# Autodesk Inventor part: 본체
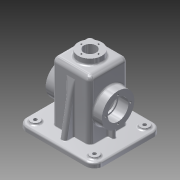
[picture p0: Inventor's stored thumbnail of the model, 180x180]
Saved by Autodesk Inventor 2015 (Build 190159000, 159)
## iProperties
Created: 2016-02
Part Number: 본체
Material: 알루미늄 6061
Document SubType Name: Modeling
Designer: Administrator
Density: 2.7 g/cm^3
Appearance: 알루미늄 - 평지
Mass: 799.421 g
Surface Area: 907.841 cm^2
Volume: 296.082 cm^3
Author: Administrator
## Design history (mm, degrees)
sketch "스케치1"
  geometry: L1 (-65, 57.5)-(65, 57.5); L2 (65, 57.5)-(65, -57.5); L3 (65, -57.5)-(-65, -57.5); L4 (-65, -57.5)-(-65, 57.5); L5 (-65, 57.5)-(65, -57.5); L6 (65, 57.5)-(-65, -57.5); 1 further point
  constraints: 12 end point, 2 midpoint, 2 parallel, 1 horizontal, 1 perpendicular
  dimensions: "d0" = 130 distance of L2.end L3.end; "d1" = 115 distance of L1.end L2.end
extrude "돌출1" new body sketch "스케치1" distance "d2" = 8; taper "d3" = 0 deg
sketch "스케치2"
  geometry: L1 (-32.5, 32.5)-(32.5, 32.5); L2 (32.5, 32.5)-(32.5, -32.5); L3 (32.5, -32.5)-(-32.5, -32.5); L4 (-32.5, -32.5)-(-32.5, 32.5); L5 (-32.5, 32.5)-(32.5, -32.5); L6 (32.5, 32.5)-(-32.5, -32.5); 1 further point
  constraints: 12 end point, 2 midpoint, 2 parallel, 1 horizontal, 1 perpendicular
  dimensions: "d4" = 65 distance of L2.end L3.end; "d5" = 65 distance of L1.end L2.end
extrude "돌출2" join sketch "스케치2" distance "d6" = 100; taper "d7" = 0 deg
sketch "스케치5"
  geometry: C1 r 20 at (0, 0); 1 further point
  constraints: 1 centre point, 1 coincident
  dimensions: "d16" = 40 diameter of C1
extrude "돌출5" join sketch "스케치5" distance "d17" = 10; taper "d18" = 0 deg
sketch "스케치7"
  geometry: L1 (-42.5, 32.753)-(-42.5, 8); L2 (65, 8)-(-65, 8) reference; L3 (-42.5, 32.753)-(42.5, 32.753); L4 (42.5, 32.753)-(42.5, 8); L5 (-32.5, 8)-(-32.5, 108) reference; 3 further points
  constraints: 6 end point, 2 point on line, 1 horizontal, 1 perpendicular, 1 vertical
  dimensions: "d23" = 24.75313 distance of L1.start L1.end; "d25" = 42.5 horizontal distance of point (0, 0) L1.end; "d26" = 42.5 distance from line of L4 point (0, 0)
extrude "돌출6" join sketch "스케치7" stored distance "d27" = 6; taper "d28" = 0 deg
sketch "스케치10"
  geometry: C1 r 7.5 at (-50, -42.5); 1 further point
  constraints: 1 centre point
  dimensions: "d39" = 15 diameter of C1; "d40" = 50 horizontal distance of point (0, 0) C1.centre; "d41" = 42.5 vertical distance of point (0, 0) C1.centre
extrude "돌출9" join sketch "스케치10" distance "d42" = 3; taper "d43" = 0 deg
sketch "스케치12"
  geometry: L1 (-65, -57.5)-(-65, 57.5) reference; L2 (-65, 57.5)-(65, 57.5) reference; L3 (65, 57.5)-(65, -57.5) reference; L4 (65, -57.5)-(-65, -57.5) reference; L5 (-60, 52.5)-(-60, -52.5); L6 (-60, -52.5)-(60, -52.5); L7 (60, -52.5)-(60, 52.5); L8 (60, 52.5)-(-60, 52.5); 1 further point
  constraints: 8 end point, 3 other
  dimensions: "d51" = 5 distance between parallel lines of L1 L5
extrude "돌출10" join sketch "스케치12" distance "d52" = 2; taper "d53" = 0 deg
sketch "스케치13"
  geometry: L1 (110, -20)-(110, 85) reference; C1 r 27.5 at (55, 32.5); 1 further point
  constraints: 1 centre point, 1 horizontal alignment
  dimensions: "d54" = 55 diameter of C1; "d55" = 55 distance from line of L1 C1.centre
extrude "돌출11" join sketch "스케치13" distance "d56" = 15; taper "d57" = 0 deg
sketch "스케치14"
  geometry: L1 (-32.5, 93.069)-(-47.5, 8); L2 (-57.5, 0)-(-57.5, 8) reference; L3 (-57.5, 8)-(57.5, 8) reference; L4 (-32.5, 8)-(-32.5, 108) reference; L5 (-47.5, 8)-(-32.5, 8); 1 further point
  constraints: 4 end point, 1 collinear, 1 horizontal alignment, 1 point on line
  dimensions: "d58" = 10 distance from line of L2 L1.end; "d59" = 100 deg angle of L3 L1
extrude "돌출12" join sketch "스케치14" stored distance "d60" = 10; taper "d61" = 0 deg
sketch "스케치15"
  geometry: L1 (27.5, 27.5)-(-27.5, 27.5); L2 (-27.5, 27.5)-(-27.5, -27.5); L3 (-27.5, -27.5)-(27.5, -27.5); L4 (27.5, -27.5)-(27.5, 27.5); L5 (27.5, 27.5)-(-27.5, -27.5); L6 (-27.5, 27.5)-(27.5, -27.5); 1 further point
  constraints: 12 end point, 2 midpoint, 2 parallel, 1 horizontal, 1 perpendicular
  dimensions: "d62" = 55 distance of L3.end L2.end; "d63" = 55 distance of L1.end L2.end
extrude "돌출13" cut sketch "스케치15" distance "d64" = 105; taper "d65" = 0 deg
sketch "스케치16"
  geometry: C1 r 7.5 at (0, 0) reference; 2 further points
  constraints: 1 coincident
hole "구멍2" sketch "스케치16" at (0, 0) diameter "d66" = 6; stored, may be unused: countersink angle "d70" = 90 deg, drill point angle "d72" = 118 deg; dims "d67" = 6, "d68" = 4, "d69" = 2, "d71" = 8
sketch "스케치20"
  geometry: C1 r 10.5 at (0, 0); 1 further point
  constraints: 1 centre point, 1 coincident
  dimensions: "d96" = 21 diameter of C1
extrude "돌출16" cut sketch "스케치20" stored distance "d97" = 3; taper "d98" = 0 deg
sketch "스케치21"
  geometry: 2 further points
  constraints: 1 vertical alignment
  dimensions: "d99" = 14.5 distance of point (0, 0) point (0, -14.5)
hole "구멍4" sketch "스케치21" at (0, -14.5) diameter "d100" = 2.459; stored, may be unused: countersink angle "d104" = 90 deg, drill point angle "d106" = 118 deg; dims "d101" = 7, "d102" = 4, "d103" = 2, "d105" = 9
fillet "모깎기2" dims "d110" = 15
fillet "모깎기3" dims "d111" = 10
sketch "스케치22"
  geometry: C1 r 27.5 at (0, 0) reference; C2 r 17.5 at (0, 0); 1 further point
  constraints: 1 centre point, 1 coincident
  dimensions: "d113" = 35 diameter of C2
extrude "돌출17" cut sketch "스케치22" distance "d114" = 17; taper "d115" = 0 deg
sketch "스케치23"
  geometry: C1 r 17.5 at (0, 0) reference; C2 r 15 at (0, 0); 1 further point
  constraints: 1 centre point, 1 coincident
  dimensions: "d116" = 30 diameter of C2
extrude "돌출18" cut sketch "스케치23" distance "d117" = 3; taper "d118" = 0 deg
fillet "모깎기5" dims "d119" = 8
fillet "모깎기8" dims "d122" = 3
fillet "모깎기9" dims "d123" = 0.3
fillet "모깎기10" dims "d124" = 3
fillet "모깎기12" dims "d126" = 3
fillet "모깎기13" dims "d130" = 8
fillet "모깎기15" dims "d132" = 3
chamfer "모따기2" distance "d133" = 1; stored, may be unused: second distance "d134" = 2, angle "d135" = 45 deg
sketch "스케치24"
  geometry: C1 r 17.5 at (0, 0) reference; C2 r 27.5 at (0, 0) reference; 2 further points
  constraints: 1 horizontal alignment
  dimensions: "d136" = 21 distance of C1.centre point (-21, 0)
hole "구멍5" sketch "스케치24" at (-21, 0) diameter "d137" = 3.242; stored, may be unused: countersink angle "d141" = 90 deg, drill point angle "d143" = 118 deg; dims "d138" = 8, "d139" = 4, "d140" = 2, "d142" = 10
node "작업 평면1"
sketch "스케치25"
  geometry: L1 (47, 32.5)-(-45, 32.5) reference; L2 (65, -20)-(65, 20) reference; 3 further points
  constraints: 1 other
  dimensions: "d148" = 32.5 distance from line of L1 point (39, 0); "d149" = 26 distance from line of point (39, 0) L2
feature "엠보싱1" sketch "스케치25" dims "d150" = 0.5, "d151" = 0
fillet "모깎기16" dims "d152" = 3
fillet "모깎기17" dims "d153" = 5
fillet "모깎기18" dims "d154" = 1
node "솔리드1"
mirror "대칭3"
mirror "대칭4"
pattern_linear "직사각형 패턴1" dims "d78" = 85
pattern_circular "원형 패턴2" dims angle "d108" = 360 deg
mirror "대칭7"
pattern_circular "원형 패턴3" dims angle "d145" = 360 deg
mirror "대칭8"
node "투영된 루프2"
node "투영된 루프6"
node "투영된 루프7"
node "투영된 루프8"
node "절단 모서리 투영3"
